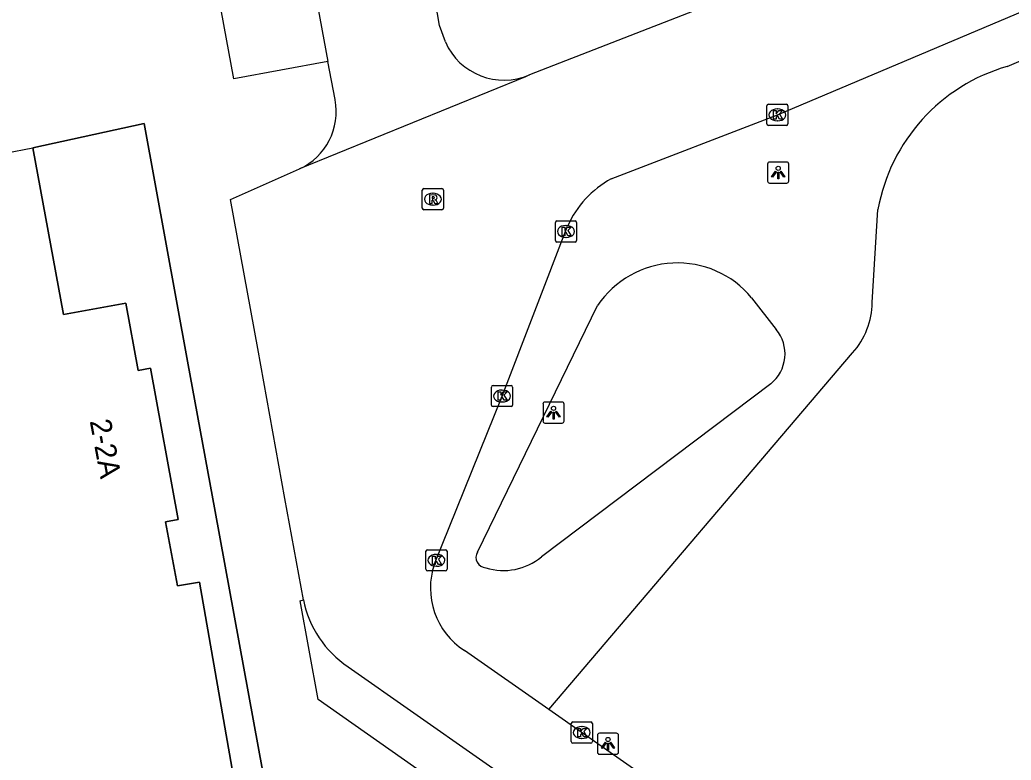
# Model space of a CAD drawing. Extents: x 159451 to 160663, y 388402 to 389723.
# Drawn here: x 159640.52 to 159687.41, y 389001.9 to 389036.93 of the extents above; entities that cross this region are included whole.
import ezdxf

# ---------------------------------------------------------------- set-up
doc = ezdxf.new("R2010")
doc.units = 0
for name, color, linetype in [('IMGEO_Erf', 7, 'Continuous'), ('IMGEO_Kolk', 7, 'Continuous'), ('IMGEO_Lichtpunt', 7, 'Continuous'), ('IMGEO_Pand', 7, 'Continuous'), ('IMGEO_Pand_nummerreeks', 7, 'Continuous'), ('IMGEO_Pand_overbouw', 7, 'Continuous'), ('IMGEO_Parkeervlak_open', 7, 'Continuous'), ('IMGEO_Rijbaan_lokaal_open', 7, 'Continuous'), ('IMGEO_Rioolput', 7, 'Continuous'), ('IMGEO_Voetpad_open', 7, 'Continuous')]:
    doc.layers.add(name, color=color, linetype=linetype)

msp = doc.modelspace()

# ---------------------------------------------------------------- linework, layer by layer
at = {"layer": 'IMGEO_Erf'}
msp.add_lwpolyline([(159641.139, 389030.865), (159646.405, 389032.016), (159648.46, 389020.775), (159649.759, 389013.67), (159658.567, 388965.49)], dxfattribs=at)
at = {"layer": 'IMGEO_Kolk'}
for p, q in [((159675.927, 389032.932), (159676.779, 389032.932)), ((159675.852, 389032.006), (159675.852, 389032.858)), ((159676.34, 389032.712), (159676.365, 389032.712)), ((159676.853, 389032.858), (159676.853, 389032.006)), ((159676.363, 389032.152), (159676.338, 389032.152)), ((159676.779, 389031.932), (159675.927, 389031.932)), ((159665.853, 389026.49), (159665.853, 389027.342)), ((159665.928, 389027.416), (159666.78, 389027.416)), ((159666.854, 389027.342), (159666.854, 389026.49)), ((159666.341, 389027.196), (159666.366, 389027.196)), ((159666.78, 389026.416), (159665.928, 389026.416)), ((159666.364, 389026.636), (159666.339, 389026.636)), ((159662.829, 389018.704), (159662.829, 389019.556)), ((159662.904, 389019.63), (159663.756, 389019.63)), ((159663.317, 389019.41), (159663.342, 389019.41)), ((159663.83, 389019.556), (159663.83, 389018.704)), ((159663.34, 389018.85), (159663.315, 389018.85)), ((159663.756, 389018.63), (159662.904, 389018.63)), ((159659.802, 389011.86), (159660.654, 389011.86)), ((159659.727, 389010.934), (159659.727, 389011.786)), ((159660.215, 389011.64), (159660.24, 389011.64)), ((159660.728, 389011.786), (159660.728, 389010.934)), ((159660.238, 389011.08), (159660.213, 389011.08)), ((159660.654, 389010.86), (159659.802, 389010.86)), ((159666.6, 389002.784), (159666.6, 389003.636)), ((159666.675, 389003.71), (159667.527, 389003.71)), ((159667.088, 389003.49), (159667.113, 389003.49)), ((159667.601, 389003.636), (159667.601, 389002.784)), ((159667.111, 389002.93), (159667.086, 389002.93)), ((159667.527, 389002.71), (159666.675, 389002.71))]:
    msp.add_line(p, q, dxfattribs=at)
for points in [[(159675.927, 389032.932), (159676.779, 389032.932)], [(159675.852, 389032.006), (159675.852, 389032.858)], [(159676.173, 389032.632), (159676.296, 389032.632), (159676.296, 389032.481), (159676.426, 389032.632), (159676.59, 389032.632), (159676.444, 389032.481), (159676.597, 389032.232), (159676.445, 389032.232), (159676.36, 389032.396), (159676.296, 389032.329), (159676.296, 389032.232), (159676.173, 389032.232), (159676.173, 389032.632)], [(159676.853, 389032.858), (159676.853, 389032.006)], [(159676.779, 389031.932), (159675.927, 389031.932)], [(159665.853, 389026.49), (159665.853, 389027.342)], [(159665.928, 389027.416), (159666.78, 389027.416)], [(159666.854, 389027.342), (159666.854, 389026.49)], [(159666.174, 389027.116), (159666.297, 389027.116), (159666.297, 389026.965), (159666.427, 389027.116), (159666.591, 389027.116), (159666.445, 389026.965), (159666.598, 389026.716), (159666.446, 389026.716), (159666.361, 389026.88), (159666.297, 389026.813), (159666.297, 389026.716), (159666.174, 389026.716), (159666.174, 389027.116)], [(159666.78, 389026.416), (159665.928, 389026.416)], [(159662.829, 389018.704), (159662.829, 389019.556)], [(159662.904, 389019.63), (159663.756, 389019.63)], [(159663.15, 389019.33), (159663.273, 389019.33), (159663.273, 389019.179), (159663.403, 389019.33), (159663.567, 389019.33), (159663.421, 389019.179), (159663.574, 389018.93), (159663.422, 389018.93), (159663.337, 389019.094), (159663.273, 389019.027), (159663.273, 389018.93), (159663.15, 389018.93), (159663.15, 389019.33)], [(159663.83, 389019.556), (159663.83, 389018.704)], [(159663.756, 389018.63), (159662.904, 389018.63)], [(159659.802, 389011.86), (159660.654, 389011.86)], [(159659.727, 389010.934), (159659.727, 389011.786)], [(159660.048, 389011.56), (159660.171, 389011.56), (159660.171, 389011.409), (159660.301, 389011.56), (159660.465, 389011.56), (159660.319, 389011.409), (159660.472, 389011.16), (159660.32, 389011.16), (159660.235, 389011.324), (159660.171, 389011.257), (159660.171, 389011.16), (159660.048, 389011.16), (159660.048, 389011.56)], [(159660.728, 389011.786), (159660.728, 389010.934)], [(159660.654, 389010.86), (159659.802, 389010.86)], [(159666.6, 389002.784), (159666.6, 389003.636)], [(159666.675, 389003.71), (159667.527, 389003.71)], [(159666.921, 389003.41), (159667.044, 389003.41), (159667.044, 389003.259), (159667.174, 389003.41), (159667.338, 389003.41), (159667.192, 389003.259), (159667.345, 389003.01), (159667.193, 389003.01), (159667.108, 389003.174), (159667.044, 389003.107), (159667.044, 389003.01), (159666.921, 389003.01), (159666.921, 389003.41)], [(159667.601, 389003.636), (159667.601, 389002.784)], [(159667.527, 389002.71), (159666.675, 389002.71)]]:
    msp.add_lwpolyline(points, dxfattribs=at)
for centre, start, end in [((159675.929, 389032.856), 91.552, 178.448), ((159675.929, 389032.856), 91.552, 178.448), ((159676.777, 389032.856), 1.552, 88.448), ((159676.777, 389032.856), 1.552, 88.448), ((159675.929, 389032.008), 181.552, 268.448), ((159675.929, 389032.008), 181.552, 268.448), ((159676.777, 389032.008), 271.552, 358.448), ((159676.777, 389032.008), 271.552, 358.448), ((159665.93, 389027.34), 91.552, 178.448), ((159665.93, 389027.34), 91.552, 178.448), ((159666.778, 389027.34), 1.552, 88.448), ((159666.778, 389027.34), 1.552, 88.448), ((159665.93, 389026.492), 181.552, 268.448), ((159665.93, 389026.492), 181.552, 268.448), ((159666.778, 389026.492), 271.552, 358.448), ((159666.778, 389026.492), 271.552, 358.448), ((159662.906, 389019.554), 91.552, 178.448), ((159662.906, 389019.554), 91.552, 178.448), ((159663.754, 389019.554), 1.552, 88.448), ((159663.754, 389019.554), 1.552, 88.448), ((159662.906, 389018.706), 181.552, 268.448), ((159662.906, 389018.706), 181.552, 268.448), ((159663.754, 389018.706), 271.552, 358.448), ((159663.754, 389018.706), 271.552, 358.448), ((159659.804, 389011.784), 91.552, 178.448), ((159659.804, 389011.784), 91.552, 178.448), ((159660.652, 389011.784), 1.552, 88.448), ((159660.652, 389011.784), 1.552, 88.448), ((159659.804, 389010.936), 181.552, 268.448), ((159659.804, 389010.936), 181.552, 268.448), ((159660.652, 389010.936), 271.552, 358.448), ((159660.652, 389010.936), 271.552, 358.448), ((159666.677, 389003.634), 91.552, 178.448), ((159666.677, 389003.634), 91.552, 178.448), ((159667.525, 389003.634), 1.552, 88.448), ((159667.525, 389003.634), 1.552, 88.448), ((159666.677, 389002.786), 181.552, 268.448), ((159666.677, 389002.786), 181.552, 268.448), ((159667.525, 389002.786), 271.552, 358.448), ((159667.525, 389002.786), 271.552, 358.448)]:
    msp.add_arc(centre, 0.0765, start, end, dxfattribs=at)
for centre, major_axis, ratio, start_param, end_param in [((159676.339, 389032.432), (-0.387, 0.002), 0.722429, 4.712389, 7.853982), ((159676.364, 389032.432), (-0.39, 0.002), 0.717154, 1.570796, 4.712389), ((159666.34, 389026.916), (-0.387, 0.002), 0.722429, 4.712389, 7.853982), ((159666.365, 389026.916), (-0.39, 0.002), 0.717154, 1.570796, 4.712389), ((159663.316, 389019.13), (-0.387, 0.002), 0.722429, 4.712389, 7.853982), ((159663.341, 389019.13), (-0.39, 0.002), 0.717154, 1.570796, 4.712389), ((159660.214, 389011.36), (-0.387, 0.002), 0.722429, 4.712389, 7.853982), ((159660.239, 389011.36), (-0.39, 0.002), 0.717154, 1.570796, 4.712389), ((159667.087, 389003.21), (-0.387, 0.002), 0.722429, 4.712389, 7.853982), ((159667.112, 389003.21), (-0.39, 0.002), 0.717154, 1.570796, 4.712389)]:
    msp.add_ellipse(centre, major_axis=major_axis, ratio=ratio, start_param=start_param, end_param=end_param, dxfattribs=at)
at = {"layer": 'IMGEO_Lichtpunt'}
for p, q in [((159675.892, 389030.104), (159675.892, 389029.297)), ((159675.892, 389030.104), (159675.892, 389029.297)), ((159676.794, 389030.199), (159675.986, 389030.199)), ((159676.794, 389030.199), (159675.986, 389030.199)), ((159676.888, 389029.297), (159676.888, 389030.104)), ((159676.888, 389029.297), (159676.888, 389030.104)), ((159675.986, 389029.203), (159676.794, 389029.203)), ((159675.986, 389029.203), (159676.794, 389029.203)), ((159666.169, 389018.845), (159665.361, 389018.845)), ((159666.169, 389018.845), (159665.361, 389018.845)), ((159665.267, 389018.75), (159665.267, 389017.943)), ((159665.267, 389018.75), (159665.267, 389017.943)), ((159666.263, 389017.943), (159666.263, 389018.75)), ((159666.263, 389017.943), (159666.263, 389018.75)), ((159665.361, 389017.849), (159666.169, 389017.849)), ((159665.361, 389017.849), (159666.169, 389017.849)), ((159667.841, 389003.086), (159667.841, 389002.279)), ((159667.841, 389003.086), (159667.841, 389002.279)), ((159668.743, 389003.181), (159667.935, 389003.181)), ((159668.743, 389003.181), (159667.935, 389003.181)), ((159668.837, 389002.279), (159668.837, 389003.086)), ((159668.837, 389002.279), (159668.837, 389003.086)), ((159667.935, 389002.185), (159668.743, 389002.185)), ((159667.935, 389002.185), (159668.743, 389002.185))]:
    msp.add_line(p, q, dxfattribs=at)
for points in [[(159676.266, 389029.768), (159676.305, 389029.74), (159676.117, 389029.478), (159676.079, 389029.505), (159676.266, 389029.768)], [(159676.368, 389029.72), (159676.415, 389029.72), (159676.415, 389029.398), (159676.368, 389029.398), (159676.368, 389029.72)], [(159676.478, 389029.74), (159676.516, 389029.767), (159676.703, 389029.505), (159676.664, 389029.477), (159676.478, 389029.74)], [(159665.641, 389018.414), (159665.68, 389018.386), (159665.492, 389018.124), (159665.454, 389018.151), (159665.641, 389018.414)], [(159665.853, 389018.386), (159665.891, 389018.413), (159666.078, 389018.151), (159666.039, 389018.123), (159665.853, 389018.386)], [(159665.743, 389018.366), (159665.79, 389018.366), (159665.79, 389018.044), (159665.743, 389018.044), (159665.743, 389018.366)], [(159668.215, 389002.75), (159668.254, 389002.722), (159668.066, 389002.46), (159668.028, 389002.487), (159668.215, 389002.75)], [(159668.317, 389002.702), (159668.364, 389002.702), (159668.364, 389002.38), (159668.317, 389002.38), (159668.317, 389002.702)], [(159668.427, 389002.722), (159668.465, 389002.749), (159668.652, 389002.487), (159668.613, 389002.459), (159668.427, 389002.722)]]:
    msp.add_lwpolyline(points, dxfattribs=at)
for centre in [(159676.391, 389029.902), (159665.766, 389018.548), (159668.34, 389002.884)]:
    msp.add_circle(centre, 0.0994, dxfattribs=at)
for centre, start, end in [((159675.986, 389030.104), 90, 180), ((159675.986, 389030.104), 90, 180), ((159676.794, 389030.104), 0, 90), ((159676.794, 389030.104), 0, 90), ((159675.986, 389029.297), 180, 270), ((159675.986, 389029.297), 180, 270), ((159676.794, 389029.297), 270, 0), ((159676.794, 389029.297), 270, 360), ((159665.361, 389018.75), 90, 180), ((159665.361, 389018.75), 90, 180), ((159666.169, 389018.75), 0, 90), ((159666.169, 389018.75), 0, 90), ((159665.361, 389017.943), 180, 270), ((159665.361, 389017.943), 180, 270), ((159666.169, 389017.943), 270, 0), ((159666.169, 389017.943), 270, 360), ((159667.935, 389003.086), 90, 180), ((159667.935, 389003.086), 90, 180), ((159668.743, 389003.086), 0, 90), ((159668.743, 389003.086), 0, 90), ((159667.935, 389002.279), 180, 270), ((159667.935, 389002.279), 180, 270), ((159668.743, 389002.279), 270, 0), ((159668.743, 389002.279), 270, 360)]:
    msp.add_arc(centre, 0.0946, start, end, dxfattribs=at)
at = {"layer": 'IMGEO_Pand'}
for points in [[(159637.189, 389030.112), (159641.139, 389030.865)], [(159658.567, 388965.49), (159657.911, 388965.294), (159654.675, 388983.049), (159653.814, 388982.885), (159649.022, 389010.328), (159647.987, 389010.149), (159647.42, 389013.176), (159648.01, 389013.284), (159646.697, 389020.449), (159646.119, 389020.344), (159645.532, 389023.528), (159642.583, 389022.991), (159641.139, 389030.865)]]:
    msp.add_lwpolyline(points, dxfattribs=at)
at = {"layer": 'IMGEO_Pand_overbouw'}
msp.add_lwpolyline([(159658.567, 388965.49), (159649.759, 389013.67), (159648.46, 389020.775), (159646.405, 389032.016), (159641.139, 389030.865), (159642.583, 389022.991), (159645.532, 389023.528), (159646.119, 389020.344), (159646.697, 389020.449), (159648.01, 389013.284), (159647.42, 389013.176), (159647.987, 389010.149), (159649.022, 389010.328), (159653.814, 388982.885), (159654.675, 388983.049), (159657.911, 388965.294)], close=True, dxfattribs=at)
at = {"layer": 'IMGEO_Parkeervlak_open'}
msp.add_lwpolyline([(159655.094, 389034.962), (159650.651, 389034.135), (159643.017, 389075.628), (159647.448, 389076.406)], dxfattribs=at)
at = {"layer": 'IMGEO_Rijbaan_lokaal_open'}
for points in [[(159647.448, 389076.406), (159655.094, 389034.962)], [(159668.491, 389029.41), (159676.353, 389032.432), (159691.434, 389038.813), (159697.167, 389041.076), (159712.428, 389046.481)], [(159660.648, 389035.879), (159660.366, 389036.656), (159659.898, 389039.432)], [(159672.696, 389037.46), (159664.635, 389034.331)], [(159655.435, 389033.151), (159655.094, 389034.962)], [(159664.635, 389034.331), (159664.437, 389034.233), (159653.757, 389029.873)], [(159653.934, 389009.489), (159653.064, 389014.277), (159651.773, 389021.385), (159650.493, 389028.426), (159653.757, 389029.873)], [(159660.132, 389011.189), (159663.33, 389019.13), (159666.428, 389027.17)], [(159665.542, 389004.294), (159661.552, 389007.089)], [(159656.057, 389006.325), (159684.003, 388986.733)], [(159685.041, 388990.631), (159665.542, 389004.294)]]:
    msp.add_lwpolyline(points, dxfattribs=at)
for centre, radius, start, end in [((159663.416, 389037.101), 3.026, 203.8137, 293.7477), ((159652.491, 389032.589), 2.997, 294.9818, 10.8026), ((159670.837, 389025.18), 4.837, 119.0074, 155.7036), ((159663.47, 389010.049), 3.527, 161.1493, 237.0569), ((159658.787, 389010.451), 4.948, 191.2138, 236.5083)]:
    msp.add_arc(centre, radius, start, end, dxfattribs=at)
at = {"layer": 'IMGEO_Rioolput'}
for p, q in [((159659.558, 389028.016), (159659.558, 389028.868)), ((159659.633, 389028.942), (159660.485, 389028.942)), ((159660.046, 389028.722), (159660.071, 389028.722)), ((159660.559, 389028.868), (159660.559, 389028.016)), ((159660.485, 389027.942), (159659.633, 389027.942)), ((159660.069, 389028.162), (159660.044, 389028.162))]:
    msp.add_line(p, q, dxfattribs=at)
for points in [[(159659.558, 389028.016), (159659.558, 389028.868)], [(159659.633, 389028.942), (159660.485, 389028.942)], [(159660.559, 389028.868), (159660.559, 389028.016)], [(159660.147, 389028.64), (159659.895, 389028.642), (159659.895, 389028.242)], [(159659.895, 389028.242), (159660.019, 389028.242), (159660.019, 389028.404), (159660.03, 389028.404)], [(159660.073, 389028.561), (159660.019, 389028.561), (159660.019, 389028.48)], [(159660.019, 389028.48), (159660.071, 389028.48)], [(159660.077, 389028.375), (159660.148, 389028.242), (159660.288, 389028.242), (159660.223, 389028.368)], [(159660.485, 389027.942), (159659.633, 389027.942)]]:
    msp.add_lwpolyline(points, dxfattribs=at)
for centre, radius, start, end in [((159659.635, 389028.866), 0.0765, 91.552, 178.448), ((159659.635, 389028.866), 0.0765, 91.552, 178.448), ((159660.483, 389028.866), 0.0765, 1.552, 88.448), ((159660.483, 389028.866), 0.0765, 1.552, 88.448), ((159660.029, 389028.351), 0.0533, 26.0293, 88.6989), ((159660.055, 389028.669), 0.19, 274.7715, 282.9687), ((159660.079, 389028.465), 0.0964, 77.0061, 93.1865), ((159660.093, 389028.522), 0.0378, 276.6634, 79.6772), ((159660.146, 389028.53), 0.109, 350.3612, 89.416), ((159660.144, 389028.53), 0.112, 277.5842, 350.9817), ((159660.128, 389028.315), 0.108, 29.5134, 73.7905), ((159659.635, 389028.018), 0.0765, 181.552, 268.448), ((159659.635, 389028.018), 0.0765, 181.552, 268.448), ((159660.483, 389028.018), 0.0765, 271.552, 358.448), ((159660.483, 389028.018), 0.0765, 271.552, 358.448)]:
    msp.add_arc(centre, radius, start, end, dxfattribs=at)
for centre, major_axis, ratio, start_param, end_param in [((159660.045, 389028.442), (-0.387, 0.002), 0.722429, 4.712389, 7.853982), ((159660.07, 389028.442), (-0.39, 0.002), 0.717154, 1.570796, 4.712389)]:
    msp.add_ellipse(centre, major_axis=major_axis, ratio=ratio, start_param=start_param, end_param=end_param, dxfattribs=at)
at = {"layer": 'IMGEO_Voetpad_open'}
for points in [[(159687.227, 389034.723), (159691.615, 389036.62), (159696.858, 389038.718), (159702.65, 389040.726), (159714.104, 389044.886), (159717.499, 389046.477)], [(159680.832, 389023.553), (159681.109, 389027.96)], [(159675.135, 389023.784), (159676.296, 389022.284)], [(159662.166, 389011.743), (159667.848, 389023.415)], [(159665.542, 389004.294), (159679.908, 389021.181)], [(159676.035, 389019.708), (159665.194, 389011.522)], [(159682.269, 388985.353), (159654.637, 389004.767), (159653.781, 389009.449), (159653.934, 389009.489)]]:
    msp.add_lwpolyline(points, dxfattribs=at)
for centre, radius, start, end in [((159689.619, 389026.411), 8.65, 106.0517, 169.6815), ((159671.63, 389020.866), 4.561, 39.7747, 146.023), ((159677.267, 389023.576), 3.566, 317.8025, 359.6312), ((159674.898, 389021.124), 1.816, 308.7576, 39.6715), ((159662.579, 389011.492), 0.483, 148.7402, 267.7122), ((159663.406, 389013.683), 2.805, 252.4425, 309.5995)]:
    msp.add_arc(centre, radius, start, end, dxfattribs=at)

# ---------------------------------------------------------------- texts
at = {"layer": 'IMGEO_Pand_nummerreeks'}
msp.add_text('2-2A', height=1, rotation=280.5709, dxfattribs=at).set_placement((159643.825, 389017.951))

doc.saveas('drawing.dxf')
